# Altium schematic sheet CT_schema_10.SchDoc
size 146 x 119 mm
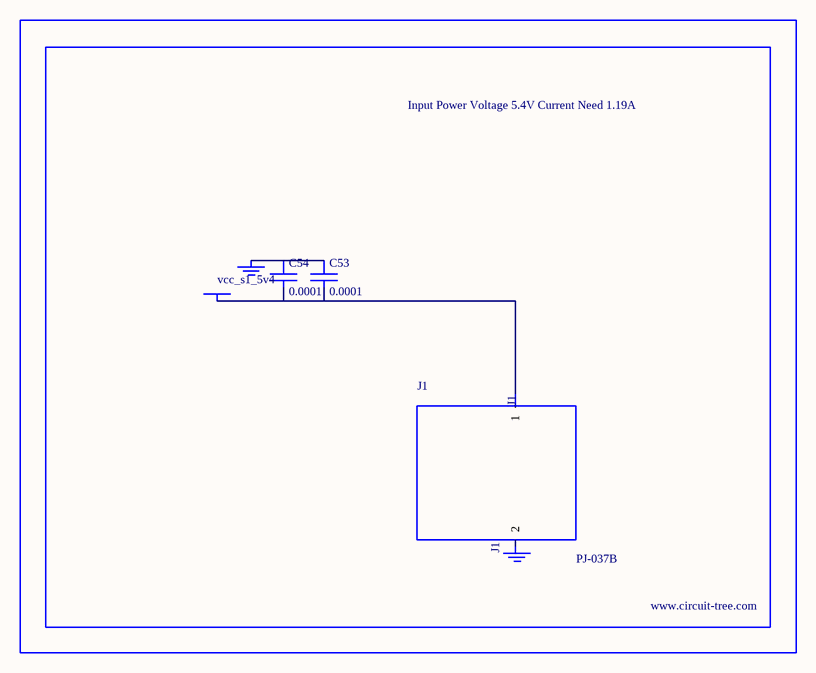
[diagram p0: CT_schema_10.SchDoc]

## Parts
BORDER9  (no value)
C53  0.0001  [EXV-9H]
C54  0.0001  [EXV-9H]
GND_INSTANCE_9_0  (no value)
GND_INSTANCE_9_1  (no value)
J1  PJ-037B  [PJ-037B_PACKAGE]
POWER_INSTANCE_9_0  vcc_s1_5v4

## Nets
NetC53_1: C53.1 C54.1 GND_INSTANCE_9_0.0(GND)
NetC53_2: C53.2 C54.2 J1.1 POWER_INSTANCE_9_0.0(PWR)

Not connected (* = marked no-connect by the designer): GND_INSTANCE_9_1 0(GND); J1 2

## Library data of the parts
BORDER9 = BORDER_PAGE9
C53 C54 = EDK107M035A9HAA
GND_INSTANCE_9_0 GND_INSTANCE_9_1 = GND
POWER_INSTANCE_9_0 = PWR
